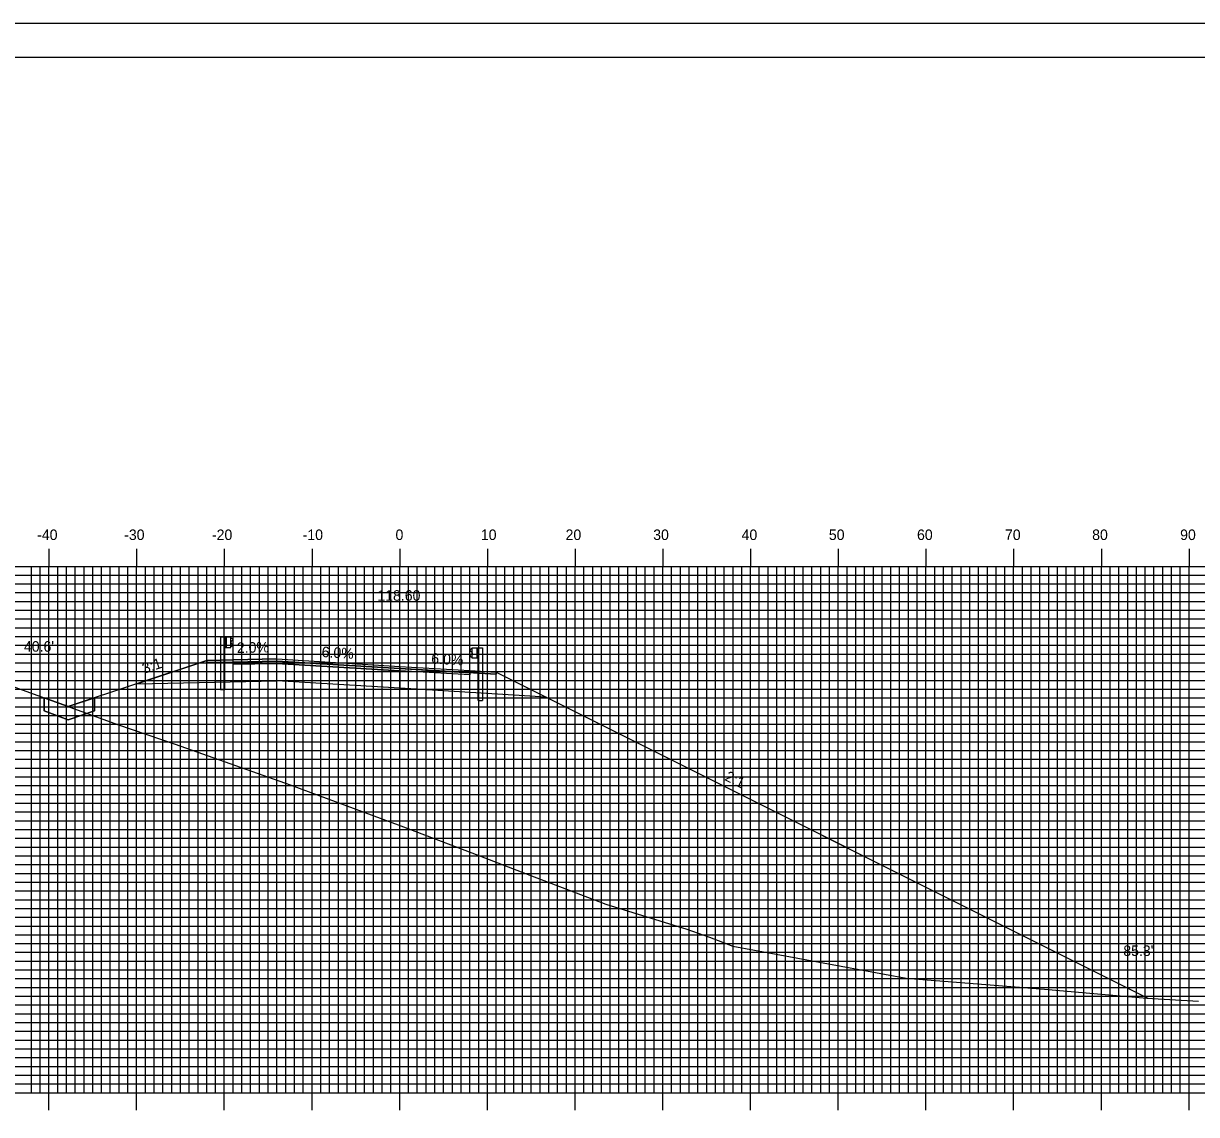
# Model space of a CAD drawing. Extents: x 858291 to 858634, y 364765 to 364985.
# Drawn here: x 858413.4 to 858547.2, y 364860.8 to 364985.2 of the extents above; entities that cross this region are included whole.
import ezdxf

# ---------------------------------------------------------------- set-up
doc = ezdxf.new("R2010")
doc.units = 0
for name, color, linetype in [('ANNOTATION', 7, 'Continuous'), ('BORDER', 7, 'Continuous'), ('D_Guardrail_Beam_Lt', 7, 'Continuous'), ('D_Guardrail_Beam_Rt', 7, 'Continuous'), ('D_Roadway_Centerline', 7, 'Continuous'), ('D_Roadway_Centerline_Text', 7, 'Continuous'), ('D_Roadway_Edge_Shoulder', 7, 'Continuous'), ('D_Roadway_Edge_TW', 7, 'Continuous'), ('D_Roadway_FinishedGrade', 7, 'Continuous'), ('D_Roadway_Pavement', 7, 'Continuous'), ('D_Roadway_SlopeLines', 7, 'Continuous'), ('D_Roadway_SubGrade', 7, 'Continuous'), ('D_Text_Standard', 7, 'Continuous'), ('H_V ANNOTATION', 7, 'Continuous'), ('MAJOR', 7, 'Continuous'), ('MINOR', 7, 'Continuous'), ('PLOT BOUNDARY', 7, 'Continuous'), ('S_Roadway_Centerline', 7, 'Continuous')]:
    doc.layers.add(name, color=color, linetype=linetype)

msp = doc.modelspace()

# ---------------------------------------------------------------- linework, layer by layer
at = {"layer": 'BORDER'}
msp.add_lwpolyline([(858306.73, 364771.3), (858626.73, 364771.3), (858626.73, 364981.3), (858306.73, 364981.3)], close=True, dxfattribs=at)
at = {"layer": 'D_Guardrail_Beam_Lt'}
for p, q in [((858435.9, 364915.22), (858435.9, 364909.22)), ((858436.38, 364915.22), (858435.9, 364915.22)), ((858437.06, 364915.22), (858436.38, 364915.22)), ((858436.38, 364915.22), (858436.38, 364914.06)), ((858436.44, 364915.22), (858436.44, 364914.06)), ((858436.54, 364915.22), (858436.54, 364914.06)), ((858437.06, 364914.06), (858437.06, 364915.22)), ((858437.06, 364915.14), (858437.14, 364915.12)), ((858437.15, 364915.12), (858437.3, 364915.02)), ((858436.38, 364914.06), (858437.06, 364914.06)), ((858436.4, 364909.22), (858436.4, 364914.06)), ((858437.14, 364914.15), (858437.06, 364914.14)), ((858437.07, 364914.67), (858437.07, 364914.6)), ((858437.3, 364914.87), (858437.1, 364914.74)), ((858437.1, 364914.54), (858437.3, 364914.4)), ((858437.3, 364914.26), (858437.15, 364914.16)), ((858436.4, 364909.22), (858435.9, 364909.22))]:
    msp.add_line(p, q, dxfattribs=at)
for centre, major_axis, start_param, end_param in [((858437.13, 364915.08), (0.0417, 0), 0.959931, 1.376053), ((858437.15, 364914.67), (-0.0789, 0), 5.323254, 6.283185), ((858437.15, 364914.6), (-0.0789, 0), 6.283185, 7.243116), ((858437.13, 364914.19), (0.0417, 0), 4.907132, 5.323254), ((858437.25, 364914.95), (0.0877, 0), 5.323254, 7.243116), ((858437.25, 364914.33), (0.0877, 0), 5.323254, 7.243116)]:
    msp.add_ellipse(centre, major_axis=major_axis, ratio=0.995501, start_param=start_param, end_param=end_param, dxfattribs=at)
at = {"layer": 'D_Guardrail_Beam_Rt'}
for p, q in [((858464.51, 364913.9), (858464.37, 364913.8)), ((858464.6, 364913.92), (858464.53, 364913.9)), ((858464.6, 364914), (858465.29, 364914)), ((858464.6, 364912.84), (858464.6, 364914)), ((858465.13, 364914), (858465.13, 364912.84)), ((858465.23, 364914), (858465.23, 364912.84)), ((858465.29, 364914), (858465.76, 364914)), ((858465.29, 364914), (858465.29, 364912.84)), ((858465.76, 364914), (858465.76, 364908)), ((858464.37, 364913.65), (858464.57, 364913.52)), ((858464.57, 364913.32), (858464.37, 364913.18)), ((858464.37, 364913.04), (858464.51, 364912.94)), ((858464.53, 364912.93), (858464.6, 364912.92)), ((858464.6, 364913.45), (858464.6, 364913.38)), ((858465.29, 364912.84), (858464.6, 364912.84)), ((858465.27, 364908), (858465.27, 364912.84)), ((858465.27, 364908), (858465.76, 364908))]:
    msp.add_line(p, q, dxfattribs=at)
for centre, major_axis, start_param, end_param in [((858464.42, 364913.73), (-0.0877, 0), 5.323254, 7.243116), ((858464.54, 364913.86), (-0.0417, 0), 4.907132, 5.323254), ((858464.42, 364913.11), (-0.0877, 0), 5.323254, 7.243116), ((858464.54, 364912.97), (-0.0417, 0), 0.959931, 1.376053), ((858464.52, 364913.45), (0.0789, 0), 0, 0.959931), ((858464.52, 364913.38), (0.0789, 0), 5.323254, 6.283185)]:
    msp.add_ellipse(centre, major_axis=major_axis, ratio=0.995501, start_param=start_param, end_param=end_param, dxfattribs=at)
at = {"layer": 'D_Roadway_Centerline'}
msp.add_lwpolyline([(858426.36, 364909.92), (858434.33, 364912.58), (858437.33, 364912.64), (858442.33, 364912.74), (858456.33, 364911.9), (858464.33, 364911.42), (858467.33, 364911.24), (858473.02, 364908.4), (858541.64, 364874.09)], dxfattribs=at)
at = {"layer": 'D_Roadway_Edge_Shoulder'}
for points in [[(858442.33, 364912.74), (858437.33, 364912.64), (858437.33, 364912.64), (858434.33, 364912.58), (858434.33, 364912.33), (858437.33, 364912.39), (858442.33, 364912.49)], [(858456.33, 364911.9), (858464.33, 364911.42), (858464.33, 364911.42), (858467.33, 364911.24), (858467.33, 364910.99), (858456.33, 364911.65)]]:
    msp.add_lwpolyline(points, close=True, dxfattribs=at)
at = {"layer": 'D_Roadway_Edge_TW'}
msp.add_lwpolyline([(858442.33, 364912.74), (858456.33, 364911.9), (858456.33, 364911.65), (858442.33, 364912.49)], close=True, dxfattribs=at)
at = {"layer": 'D_Roadway_FinishedGrade'}
for points in [[(858421.53, 364908.31), (858421.53, 364906.81), (858418.53, 364905.81), (858415.79, 364906.81), (858415.79, 364908.31), (858418.53, 364907.31)], [(858415.79, 364908.31), (858415.79, 364906.81), (858418.53, 364905.81), (858421.53, 364906.81), (858421.53, 364908.31), (858418.53, 364907.31)]]:
    msp.add_lwpolyline(points, close=True, dxfattribs=at)
at = {"layer": 'D_Roadway_Pavement'}
for points in [[(858442.33, 364912.49), (858437.33, 364912.39), (858437.33, 364912.14), (858442.33, 364912.24)], [(858442.33, 364912.49), (858456.33, 364911.65), (858456.33, 364911.4), (858442.33, 364912.24)]]:
    msp.add_lwpolyline(points, close=True, dxfattribs=at)
for points in [[(858456.33, 364911.65), (858456.33, 364911.4)], [(858456.33, 364911.65), (858456.33, 364911.4)], [(858456.33, 364911.65), (858456.33, 364911.4)], [(858456.33, 364911.65), (858464.33, 364911.17), (858464.33, 364910.92), (858456.33, 364911.4)]]:
    msp.add_lwpolyline(points, dxfattribs=at)
at = {"layer": 'D_Roadway_SlopeLines'}
msp.add_line((858434.33, 364912.58), (858418.53, 364907.31), dxfattribs=at)
msp.add_lwpolyline([(858467.33, 364911.24), (858541.64, 364874.09)], dxfattribs=at)
at = {"layer": 'D_Roadway_SubGrade'}
for points in [[(858442.33, 364912.24), (858437.33, 364912.14), (858437.33, 364912.39), (858434.33, 364912.33), (858434.33, 364912.58), (858426.36, 364909.92), (858442.33, 364910.24)], [(858442.33, 364912.24), (858456.33, 364911.4), (858456.33, 364909.4), (858442.33, 364910.24)], [(858456.33, 364911.4), (858456.33, 364911.65), (858467.33, 364910.99), (858467.33, 364911.24), (858473.02, 364908.4), (858456.33, 364909.4)]]:
    msp.add_lwpolyline(points, close=True, dxfattribs=at)
at = {"layer": 'MAJOR'}
for p, q in [((858416.33, 364925.31), (858416.33, 364923.3)), ((858426.33, 364925.31), (858426.33, 364923.3)), ((858436.33, 364925.31), (858436.33, 364923.3)), ((858446.33, 364925.31), (858446.33, 364923.3)), ((858456.33, 364925.31), (858456.33, 364923.3)), ((858466.33, 364925.31), (858466.33, 364923.3)), ((858476.33, 364925.31), (858476.33, 364923.3)), ((858486.33, 364925.31), (858486.33, 364923.3)), ((858496.33, 364925.31), (858496.33, 364923.3)), ((858506.33, 364925.31), (858506.33, 364923.3)), ((858516.33, 364925.31), (858516.33, 364923.3)), ((858526.33, 364925.31), (858526.33, 364923.3)), ((858536.33, 364925.31), (858536.33, 364923.3)), ((858546.33, 364925.31), (858546.33, 364923.3)), ((858316.33, 364923.3), (858596.33, 364923.3)), ((858316.33, 364923.3), (858596.33, 364923.3)), ((858416.33, 364863.3), (858416.33, 364923.3)), ((858426.33, 364863.3), (858426.33, 364923.3)), ((858436.33, 364863.3), (858436.33, 364923.3)), ((858446.33, 364863.3), (858446.33, 364923.3)), ((858456.33, 364863.3), (858456.33, 364923.3)), ((858466.33, 364863.3), (858466.33, 364923.3)), ((858476.33, 364863.3), (858476.33, 364923.3)), ((858486.33, 364863.3), (858486.33, 364923.3)), ((858496.33, 364863.3), (858496.33, 364923.3)), ((858506.33, 364863.3), (858506.33, 364923.3)), ((858516.33, 364863.3), (858516.33, 364923.3)), ((858526.33, 364863.3), (858526.33, 364923.3)), ((858536.33, 364863.3), (858536.33, 364923.3)), ((858546.33, 364863.3), (858546.33, 364923.3)), ((858316.33, 364918.3), (858596.33, 364918.3)), ((858316.33, 364913.3), (858596.33, 364913.3)), ((858316.33, 364908.3), (858596.33, 364908.3)), ((858316.33, 364903.3), (858596.33, 364903.3)), ((858316.33, 364898.3), (858596.33, 364898.3)), ((858316.33, 364893.3), (858596.33, 364893.3)), ((858316.33, 364888.3), (858596.33, 364888.3)), ((858316.33, 364883.3), (858596.33, 364883.3)), ((858316.33, 364878.3), (858596.33, 364878.3)), ((858316.33, 364873.3), (858596.33, 364873.3)), ((858316.33, 364868.3), (858596.33, 364868.3)), ((858316.33, 364863.3), (858596.33, 364863.3)), ((858316.33, 364863.3), (858596.33, 364863.3)), ((858416.33, 364861.3), (858416.33, 364863.3)), ((858426.33, 364861.3), (858426.33, 364863.3)), ((858436.33, 364861.3), (858436.33, 364863.3)), ((858446.33, 364861.3), (858446.33, 364863.3)), ((858456.33, 364861.3), (858456.33, 364863.3)), ((858466.33, 364861.3), (858466.33, 364863.3)), ((858476.33, 364861.3), (858476.33, 364863.3)), ((858486.33, 364861.3), (858486.33, 364863.3)), ((858496.33, 364861.3), (858496.33, 364863.3)), ((858506.33, 364861.3), (858506.33, 364863.3)), ((858516.33, 364861.3), (858516.33, 364863.3)), ((858526.33, 364861.3), (858526.33, 364863.3)), ((858536.33, 364861.3), (858536.33, 364863.3)), ((858546.33, 364861.3), (858546.33, 364863.3))]:
    msp.add_line(p, q, dxfattribs=at)
at = {"layer": 'MINOR'}
for p, q in [((858414.33, 364863.3), (858414.33, 364923.3)), ((858415.33, 364863.3), (858415.33, 364923.3)), ((858417.33, 364863.3), (858417.33, 364923.3)), ((858418.33, 364863.3), (858418.33, 364923.3)), ((858419.33, 364863.3), (858419.33, 364923.3)), ((858420.33, 364863.3), (858420.33, 364923.3)), ((858421.33, 364863.3), (858421.33, 364923.3)), ((858422.33, 364863.3), (858422.33, 364923.3)), ((858423.33, 364863.3), (858423.33, 364923.3)), ((858424.33, 364863.3), (858424.33, 364923.3)), ((858425.33, 364863.3), (858425.33, 364923.3)), ((858427.33, 364863.3), (858427.33, 364923.3)), ((858428.33, 364863.3), (858428.33, 364923.3)), ((858429.33, 364863.3), (858429.33, 364923.3)), ((858430.33, 364863.3), (858430.33, 364923.3)), ((858431.33, 364863.3), (858431.33, 364923.3)), ((858432.33, 364863.3), (858432.33, 364923.3)), ((858433.33, 364863.3), (858433.33, 364923.3)), ((858434.33, 364863.3), (858434.33, 364923.3)), ((858435.33, 364863.3), (858435.33, 364923.3)), ((858437.33, 364863.3), (858437.33, 364923.3)), ((858438.33, 364863.3), (858438.33, 364923.3)), ((858439.33, 364863.3), (858439.33, 364923.3)), ((858440.33, 364863.3), (858440.33, 364923.3)), ((858441.33, 364863.3), (858441.33, 364923.3)), ((858442.33, 364863.3), (858442.33, 364923.3)), ((858443.33, 364863.3), (858443.33, 364923.3)), ((858444.33, 364863.3), (858444.33, 364923.3)), ((858445.33, 364863.3), (858445.33, 364923.3)), ((858447.33, 364863.3), (858447.33, 364923.3)), ((858448.33, 364863.3), (858448.33, 364923.3)), ((858449.33, 364863.3), (858449.33, 364923.3)), ((858450.33, 364863.3), (858450.33, 364923.3)), ((858451.33, 364863.3), (858451.33, 364923.3)), ((858452.33, 364863.3), (858452.33, 364923.3)), ((858453.33, 364863.3), (858453.33, 364923.3)), ((858454.33, 364863.3), (858454.33, 364923.3)), ((858455.33, 364863.3), (858455.33, 364923.3)), ((858457.33, 364863.3), (858457.33, 364923.3)), ((858458.33, 364863.3), (858458.33, 364923.3)), ((858459.33, 364863.3), (858459.33, 364923.3)), ((858460.33, 364863.3), (858460.33, 364923.3)), ((858461.33, 364863.3), (858461.33, 364923.3)), ((858462.33, 364863.3), (858462.33, 364923.3)), ((858463.33, 364863.3), (858463.33, 364923.3)), ((858464.33, 364863.3), (858464.33, 364923.3)), ((858465.33, 364863.3), (858465.33, 364923.3)), ((858467.33, 364863.3), (858467.33, 364923.3)), ((858468.33, 364863.3), (858468.33, 364923.3)), ((858469.33, 364863.3), (858469.33, 364923.3)), ((858470.33, 364863.3), (858470.33, 364923.3)), ((858471.33, 364863.3), (858471.33, 364923.3)), ((858472.33, 364863.3), (858472.33, 364923.3)), ((858473.33, 364863.3), (858473.33, 364923.3)), ((858474.33, 364863.3), (858474.33, 364923.3)), ((858475.33, 364863.3), (858475.33, 364923.3)), ((858477.33, 364863.3), (858477.33, 364923.3)), ((858478.33, 364863.3), (858478.33, 364923.3)), ((858479.33, 364863.3), (858479.33, 364923.3)), ((858480.33, 364863.3), (858480.33, 364923.3)), ((858481.33, 364863.3), (858481.33, 364923.3)), ((858482.33, 364863.3), (858482.33, 364923.3)), ((858483.33, 364863.3), (858483.33, 364923.3)), ((858484.33, 364863.3), (858484.33, 364923.3)), ((858485.33, 364863.3), (858485.33, 364923.3)), ((858487.33, 364863.3), (858487.33, 364923.3)), ((858488.33, 364863.3), (858488.33, 364923.3)), ((858489.33, 364863.3), (858489.33, 364923.3)), ((858490.33, 364863.3), (858490.33, 364923.3)), ((858491.33, 364863.3), (858491.33, 364923.3)), ((858492.33, 364863.3), (858492.33, 364923.3)), ((858493.33, 364863.3), (858493.33, 364923.3)), ((858494.33, 364863.3), (858494.33, 364923.3)), ((858495.33, 364863.3), (858495.33, 364923.3)), ((858497.33, 364863.3), (858497.33, 364923.3)), ((858498.33, 364863.3), (858498.33, 364923.3)), ((858499.33, 364863.3), (858499.33, 364923.3)), ((858500.33, 364863.3), (858500.33, 364923.3)), ((858501.33, 364863.3), (858501.33, 364923.3)), ((858502.33, 364863.3), (858502.33, 364923.3)), ((858503.33, 364863.3), (858503.33, 364923.3)), ((858504.33, 364863.3), (858504.33, 364923.3)), ((858505.33, 364863.3), (858505.33, 364923.3)), ((858507.33, 364863.3), (858507.33, 364923.3)), ((858508.33, 364863.3), (858508.33, 364923.3)), ((858509.33, 364863.3), (858509.33, 364923.3)), ((858510.33, 364863.3), (858510.33, 364923.3)), ((858511.33, 364863.3), (858511.33, 364923.3)), ((858512.33, 364863.3), (858512.33, 364923.3)), ((858513.33, 364863.3), (858513.33, 364923.3)), ((858514.33, 364863.3), (858514.33, 364923.3)), ((858515.33, 364863.3), (858515.33, 364923.3)), ((858517.33, 364863.3), (858517.33, 364923.3)), ((858518.33, 364863.3), (858518.33, 364923.3)), ((858519.33, 364863.3), (858519.33, 364923.3)), ((858520.33, 364863.3), (858520.33, 364923.3)), ((858521.33, 364863.3), (858521.33, 364923.3)), ((858522.33, 364863.3), (858522.33, 364923.3)), ((858523.33, 364863.3), (858523.33, 364923.3)), ((858524.33, 364863.3), (858524.33, 364923.3)), ((858525.33, 364863.3), (858525.33, 364923.3)), ((858527.33, 364863.3), (858527.33, 364923.3)), ((858528.33, 364863.3), (858528.33, 364923.3)), ((858529.33, 364863.3), (858529.33, 364923.3)), ((858530.33, 364863.3), (858530.33, 364923.3)), ((858531.33, 364863.3), (858531.33, 364923.3)), ((858532.33, 364863.3), (858532.33, 364923.3)), ((858533.33, 364863.3), (858533.33, 364923.3)), ((858534.33, 364863.3), (858534.33, 364923.3)), ((858535.33, 364863.3), (858535.33, 364923.3)), ((858537.33, 364863.3), (858537.33, 364923.3)), ((858538.33, 364863.3), (858538.33, 364923.3)), ((858539.33, 364863.3), (858539.33, 364923.3)), ((858540.33, 364863.3), (858540.33, 364923.3)), ((858541.33, 364863.3), (858541.33, 364923.3)), ((858542.33, 364863.3), (858542.33, 364923.3)), ((858543.33, 364863.3), (858543.33, 364923.3)), ((858544.33, 364863.3), (858544.33, 364923.3)), ((858545.33, 364863.3), (858545.33, 364923.3)), ((858316.33, 364922.3), (858596.33, 364922.3)), ((858316.33, 364921.3), (858596.33, 364921.3)), ((858316.33, 364920.3), (858596.33, 364920.3)), ((858316.33, 364919.3), (858596.33, 364919.3)), ((858316.33, 364917.3), (858596.33, 364917.3)), ((858316.33, 364916.3), (858596.33, 364916.3)), ((858316.33, 364915.3), (858596.33, 364915.3)), ((858316.33, 364914.3), (858596.33, 364914.3)), ((858316.33, 364912.3), (858596.33, 364912.3)), ((858316.33, 364911.3), (858596.33, 364911.3)), ((858316.33, 364910.3), (858596.33, 364910.3)), ((858316.33, 364909.3), (858596.33, 364909.3)), ((858316.33, 364907.3), (858596.33, 364907.3)), ((858316.33, 364906.3), (858596.33, 364906.3)), ((858316.33, 364905.3), (858596.33, 364905.3)), ((858316.33, 364904.3), (858596.33, 364904.3)), ((858316.33, 364902.3), (858596.33, 364902.3)), ((858316.33, 364901.3), (858596.33, 364901.3)), ((858316.33, 364900.3), (858596.33, 364900.3)), ((858316.33, 364899.3), (858596.33, 364899.3)), ((858316.33, 364897.3), (858596.33, 364897.3)), ((858316.33, 364896.3), (858596.33, 364896.3)), ((858316.33, 364895.3), (858596.33, 364895.3)), ((858316.33, 364894.3), (858596.33, 364894.3)), ((858316.33, 364892.3), (858596.33, 364892.3)), ((858316.33, 364891.3), (858596.33, 364891.3)), ((858316.33, 364890.3), (858596.33, 364890.3)), ((858316.33, 364889.3), (858596.33, 364889.3)), ((858316.33, 364887.3), (858596.33, 364887.3)), ((858316.33, 364886.3), (858596.33, 364886.3)), ((858316.33, 364885.3), (858596.33, 364885.3)), ((858316.33, 364884.3), (858596.33, 364884.3)), ((858316.33, 364882.3), (858596.33, 364882.3)), ((858316.33, 364881.3), (858596.33, 364881.3)), ((858316.33, 364880.3), (858596.33, 364880.3)), ((858316.33, 364879.3), (858596.33, 364879.3)), ((858316.33, 364877.3), (858596.33, 364877.3)), ((858316.33, 364876.3), (858596.33, 364876.3)), ((858316.33, 364875.3), (858596.33, 364875.3)), ((858316.33, 364874.3), (858596.33, 364874.3)), ((858316.33, 364872.3), (858596.33, 364872.3)), ((858316.33, 364871.3), (858596.33, 364871.3)), ((858316.33, 364870.3), (858596.33, 364870.3)), ((858316.33, 364869.3), (858596.33, 364869.3)), ((858316.33, 364867.3), (858596.33, 364867.3)), ((858316.33, 364866.3), (858596.33, 364866.3)), ((858316.33, 364865.3), (858596.33, 364865.3)), ((858316.33, 364864.3), (858596.33, 364864.3))]:
    msp.add_line(p, q, dxfattribs=at)
at = {"layer": 'PLOT BOUNDARY'}
msp.add_lwpolyline([(858290.55, 364765.18), (858630.55, 364765.18), (858630.55, 364985.18), (858290.55, 364985.18)], close=True, dxfattribs=at)
at = {"layer": 'S_Roadway_Centerline'}
msp.add_lwpolyline([(858410.89, 364910.1), (858424.16, 364905.26), (858430.74, 364903.02), (858443.83, 364898.4), (858456.45, 364893.73), (858464.55, 364890.64), (858471.18, 364888.09), (858479.83, 364884.79), (858489.06, 364881.94), (858491.65, 364881.02), (858494.31, 364880.01), (858511.62, 364876.8), (858514.08, 364876.37), (858529.84, 364875.11), (858541.53, 364874.09), (858547.42, 364873.73)], dxfattribs=at)

# ---------------------------------------------------------------- texts
at = {"layer": 'ANNOTATION'}
for s, rotation, p in [('2.0%', 1.1458, (858437.77, 364913.42)), ('6.0%', 356.5664, (858447.4, 364912.97)), ('3:1', 18.4349, (858427.19, 364911.05)), ('6.0%', 356.5664, (858459.9, 364912.22)), ('2:1', 333.3359, (858493.3, 364898.96))]:
    msp.add_text(s, height=1.2, rotation=rotation, dxfattribs=at).set_placement(p)
at = {"layer": 'D_Roadway_Centerline_Text'}
msp.add_text('118.60', height=1.2, dxfattribs=at).set_placement((858453.78, 364919.38))
at = {"layer": 'D_Text_Standard'}
for s, p in [("40.6'", (858413.48, 364913.57)), ("85.3'", (858538.83, 364878.88))]:
    msp.add_text(s, height=1.2, dxfattribs=at).set_placement(p)
at = {"layer": 'H_V ANNOTATION'}
for s, p in [('-40', (858414.99, 364926.3)), ('-30', (858424.91, 364926.3)), ('-20', (858434.92, 364926.3)), ('-10', (858445.26, 364926.3)), ('0', (858455.85, 364926.3)), ('10', (858465.58, 364926.3)), ('20', (858475.24, 364926.3)), ('30', (858485.23, 364926.3)), ('40', (858495.31, 364926.3)), ('50', (858505.26, 364926.3)), ('60', (858515.31, 364926.3)), ('70', (858525.34, 364926.3)), ('80', (858535.28, 364926.3)), ('90', (858545.31, 364926.3))]:
    msp.add_text(s, height=1.2, dxfattribs=at).set_placement(p)

doc.saveas('drawing.dxf')
